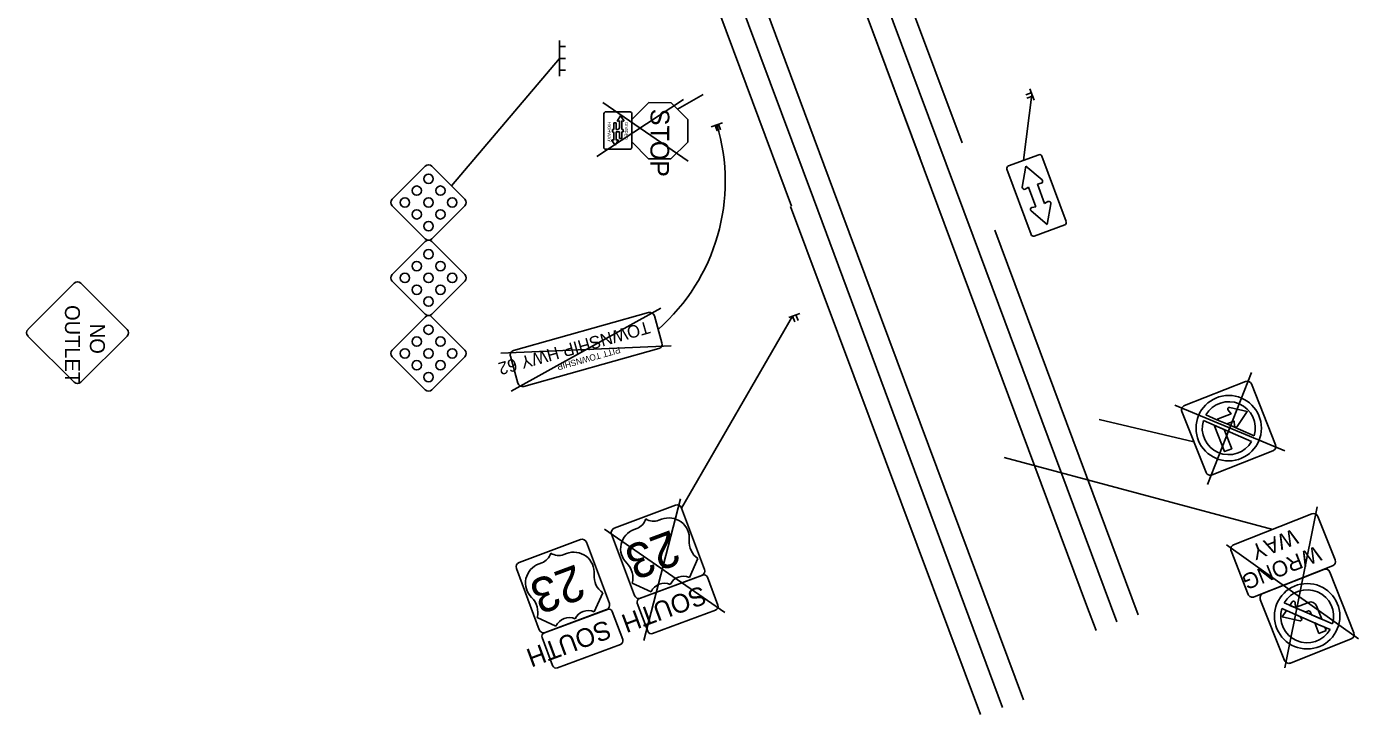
# Model space of a CAD drawing. Extents: x 179840 to 180553, y 300239 to 301090.
# Drawn here: x 179840 to 180553, y 300239 to 300607 of the extents above; entities that cross this region are included whole.
import ezdxf

# ---------------------------------------------------------------- set-up
doc = ezdxf.new("R2010")
doc.units = 0
for name, color, linetype in [('DR_P_Ditch', 7, 'Continuous'), ('MT_P_CL_40', 7, 'Continuous'), ('PM_P_Edge_Line', 7, 'Continuous'), ('PV_P_Saw_Cut_Line', 7, 'Continuous'), ('PV_X_Shoulder_Aggregate', 7, 'Continuous'), ('RW_P_Const_Limits', 7, 'Continuous')]:
    doc.layers.add(name, color=color, linetype=linetype)

msp = doc.modelspace()

# ---------------------------------------------------------------- linework, layer by layer
at = {"layer": 'DR_P_Ditch'}
for p, q in [((180407.15, 300297.25), (180248.33, 300723.77)), ((180271.8, 300519.09), (180373.45, 300246.68)), ((180248.77, 300510.52), (180350.47, 300238.9)), ((180358.06, 300497.86), (180434.85, 300292.18)), ((180407.15, 300297.25), (180412.37, 300283.81))]:
    msp.add_line(p, q, dxfattribs=at)
at = {"layer": 'MT_P_CL_40'}
for p, q in [((180346.46, 300494.63), (180276.74, 300681.88)), ((180261.02, 300514.81), (180362.15, 300242.51)), ((180346.46, 300494.63), (180423.45, 300288.43))]:
    msp.add_line(p, q, dxfattribs=at)
at = {"layer": 'PM_P_Edge_Line'}
for p, q in [((180200.42, 300919.36), (180340.54, 300544.7)), ((180178.69, 300911.24), (180318.13, 300536.33)), ((180132.45, 300894.04), (180271.8, 300519.09)), ((180179.58, 300698.16), (180249.31, 300510.72))]:
    msp.add_line(p, q, dxfattribs=at)
at = {"layer": 'PV_P_Saw_Cut_Line'}
for p, q in [((180125.19, 300592.98), (180125.19, 300599.38)), ((180125.19, 300596.18), (180128.39, 300596.18)), ((180125.19, 300589.84), (180067.4, 300521.71)), ((180125.19, 300586.64), (180125.19, 300593.04)), ((180125.19, 300589.84), (180128.39, 300589.84)), ((180125.19, 300580.24), (180125.19, 300586.64)), ((180125.19, 300583.44), (180128.39, 300583.44)), ((180191.46, 300567.82), (180145.18, 300537.41)), ((180148.39, 300566.3), (180193.95, 300534.81)), ((180099.3, 300411.83), (180179.42, 300456.17)), ((180247.8, 300451.13), (180253.79, 300453.38)), ((180251.69, 300452.59), (180252.82, 300449.6)), ((180249.9, 300451.92), (180251.02, 300448.92)), ((180250.79, 300452.26), (180250.79, 300452.26)), ((180093.74, 300432.15), (180184.99, 300435.97)), ((180471.9, 300361.92), (180495.43, 300421.74)), ((180513.18, 300379.96), (180454.45, 300404.23)), ((180170.37, 300278.42), (180189.97, 300354.16)), ((180513.27, 300263.75), (180530.54, 300349.87)), ((180149.35, 300337.93), (180213.65, 300293.36)), ((180128.9, 300324.92), (180127.43, 300324.38)), ((180552.59, 300279.24), (180482.09, 300329.59)), ((180115.72, 300320.02), (180114.25, 300319.47)), ((180143.81, 300293.79), (180148.41, 300303.84)), ((180113.26, 300290.76), (180123.31, 300286.16)), ((180117.13, 300282.53), (180150.87, 300295.08)), ((180153.44, 300293.91), (180159.02, 300278.91)), ((180121.53, 300264.96), (180115.95, 300279.96)), ((180157.84, 300276.34), (180124.1, 300263.79))]:
    msp.add_line(p, q, dxfattribs=at)
for points in [[(180053.4, 300532.17), (180035.72, 300514.49)], [(180074.61, 300514.49), (180056.93, 300532.17)], [(180035.72, 300510.96), (180053.4, 300493.28)], [(180056.93, 300493.28), (180074.61, 300510.96)], [(180053.4, 300491.82), (180035.72, 300474.14)], [(180074.61, 300474.14), (180056.93, 300491.82)], [(179840.84, 300444.84), (179865.59, 300469.59)], [(179869.13, 300469.59), (179893.88, 300444.84)], [(180035.72, 300470.6), (180053.4, 300452.92)], [(180056.93, 300452.92), (180074.61, 300470.6)], [(180053.4, 300451.46), (180035.72, 300433.78)], [(180074.61, 300433.78), (180056.93, 300451.46)], [(179865.59, 300416.56), (179840.84, 300441.3)], [(179893.88, 300441.3), (179869.13, 300416.56)], [(180035.72, 300430.25), (180053.4, 300412.57)], [(180056.93, 300412.57), (180074.61, 300430.25)], [(180136.45, 300332.4), (180103.65, 300320.2)], [(180151.87, 300298.12), (180139.67, 300330.93)], [(180102.18, 300316.98), (180114.38, 300284.18)], [(180117.59, 300282.71), (180150.4, 300294.91)]]:
    msp.add_lwpolyline(points, dxfattribs=at)
for centre in [(180055.16, 300525.39), (180048.83, 300519.06), (180061.5, 300519.06), (180042.5, 300512.73), (180055.16, 300512.73), (180067.83, 300512.73), (180048.83, 300506.39), (180055.16, 300500.06), (180061.5, 300506.39), (180048.83, 300478.7), (180055.16, 300485.04), (180061.5, 300478.7), (180042.5, 300472.37), (180055.16, 300472.37), (180067.83, 300472.37), (180048.83, 300466.04), (180061.5, 300466.04), (180055.16, 300459.7), (180055.16, 300444.68), (180048.83, 300438.35), (180061.5, 300438.35), (180042.5, 300432.01), (180055.16, 300432.01), (180067.83, 300432.01), (180048.83, 300425.68), (180061.5, 300425.68), (180055.16, 300419.35)]:
    msp.add_circle(centre, 2.5, dxfattribs=at)
for centre, radius, start, end in [((180055.16, 300530.4), 2.5, 45, 135), ((180037.49, 300512.73), 2.5, 135, 225), ((180072.84, 300512.73), 2.5, 315, 45), ((180055.16, 300495.05), 2.5, 225, 315), ((180055.16, 300490.05), 2.5, 45, 135), ((180037.49, 300472.37), 2.5, 135, 225), ((180072.84, 300472.37), 2.5, 315, 45), ((179867.36, 300467.82), 2.5, 45, 135), ((180055.16, 300454.69), 2.5, 225, 315), ((180055.16, 300449.69), 2.5, 45, 135), ((179842.61, 300443.07), 2.5, 135, 225), ((179892.11, 300443.07), 2.5, 315, 45), ((180037.49, 300432.01), 2.5, 135, 225), ((180072.84, 300432.01), 2.5, 315, 45), ((179867.36, 300418.32), 2.5, 225, 315), ((180055.16, 300414.34), 2.5, 225, 315), ((180137.32, 300330.06), 2.5, 20.40473, 110.40473), ((180112.99, 300327.34), 7.81, 290.40473, 343.53483), ((180124.71, 300331.7), 7.81, 237.27462, 290.40473), ((180132.82, 300314.71), 10.94, 355.23665, 111.04299), ((180104.52, 300317.85), 2.5, 110.40473, 200.40473), ((180117.95, 300309.18), 10.94, 109.76646, 225.57281), ((180154.62, 300312.84), 10.94, 174.95185, 235.40566), ((180102.68, 300293.52), 10.94, 345.4038, 45.8576), ((180149.53, 300297.25), 2.5, 290.40473, 20.40473), ((180130.38, 300282.84), 7.81, 65.97772, 154.83173), ((180140.63, 300286.66), 7.81, 65.97772, 154.83173), ((180151.56, 300293.21), 2, 20.40473, 110.40473), ((180116.72, 300285.05), 2.5, 200.40473, 290.40473), ((180117.82, 300280.66), 2, 110.40473, 200.40473), ((180157.14, 300278.21), 2, 290.40473, 20.40473), ((180123.4, 300265.66), 2, 200.40473, 290.40473)]:
    msp.add_arc(centre, radius, start, end, dxfattribs=at)
at = {"layer": 'PV_X_Shoulder_Aggregate'}
msp.add_line((180191.6, 300700.84), (180261.02, 300514.81), dxfattribs=at)
at = {"layer": 'RW_P_Const_Limits'}
for p, q in [((180376.82, 300573.5), (180379.06, 300567.5)), ((180188.4, 300562.62), (180202.01, 300570.48)), ((180373.49, 300535.3), (180377.94, 300570.5)), ((180377.61, 300571.4), (180374.61, 300570.28)), ((180378.28, 300569.6), (180375.28, 300568.48)), ((180377.94, 300570.5), (180377.94, 300570.5)), ((180148.86, 300542.25), (180148.94, 300560.25)), ((180149.95, 300561.24), (180162.95, 300561.18)), ((180163.94, 300560.18), (180163.86, 300542.18)), ((180172.97, 300566.14), (180163.93, 300557.18)), ((180184.97, 300566.08), (180172.97, 300566.14)), ((180193.93, 300557.04), (180184.97, 300566.08)), ((180154.34, 300555.39), (180154.32, 300551.85)), ((180155.59, 300555.38), (180154.34, 300555.39)), ((180155.57, 300551.84), (180155.59, 300555.38)), ((180157.9, 300559.12), (180156.24, 300556.61)), ((180156.57, 300556.16), (180157.26, 300556.35)), ((180157.26, 300556.35), (180157.25, 300552.67)), ((180159.54, 300556.6), (180157.9, 300559.12)), ((180158.49, 300551.83), (180158.51, 300556.34)), ((180158.51, 300556.34), (180159.19, 300556.15)), ((180159.53, 300556.6), (180159.54, 300556.6)), ((180163.93, 300557.18), (180163.87, 300545.18)), ((180193.87, 300545.04), (180193.93, 300557.04)), ((180206.41, 300553.23), (180212.42, 300555.42)), ((180208.52, 300554), (180209.61, 300550.99)), ((180209.42, 300554.33), (180209.42, 300554.33)), ((180210.32, 300554.66), (180211.41, 300551.65)), ((180153.27, 300545.83), (180154.91, 300543.31)), ((180153.49, 300551.85), (180153.48, 300550.6)), ((180153.48, 300550.6), (180153.49, 300550.6)), ((180154.32, 300551.85), (180153.49, 300551.85)), ((180154.3, 300546.1), (180153.61, 300546.3)), ((180154.31, 300549.77), (180154.3, 300546.1)), ((180154.91, 300543.31), (180156.57, 300545.81)), ((180155.55, 300546.09), (180155.57, 300550.59)), ((180156.24, 300546.28), (180155.55, 300546.09)), ((180156.41, 300551.84), (180155.57, 300551.84)), ((180155.57, 300550.59), (180157.24, 300550.59)), ((180157.24, 300550.59), (180157.22, 300547.05)), ((180157.22, 300547.05), (180158.47, 300547.04)), ((180158.47, 300547.04), (180158.49, 300550.58)), ((180159.32, 300551.83), (180158.49, 300551.83)), ((180158.49, 300550.58), (180159.32, 300550.58)), ((180159.32, 300550.58), (180159.32, 300551.83)), ((180163.87, 300545.18), (180172.83, 300536.14)), ((180184.83, 300536.08), (180193.87, 300545.04)), ((180162.85, 300541.18), (180149.85, 300541.24)), ((180184.83, 300536.08), (180172.83, 300536.14)), ((180172.83, 300536.14), (180184.83, 300536.08)), ((180172.83, 300536.14), (180184.83, 300536.08)), ((180374.64, 300532.17), (180372.77, 300520.97)), ((180383.34, 300524.86), (180374.64, 300532.17)), ((180374.27, 300519.87), (180376.15, 300520.85)), ((180376.15, 300520.85), (180379.97, 300510.49)), ((180384.66, 300512.22), (180380.84, 300522.58)), ((180380.85, 300522.58), (180382.91, 300523.06)), ((180379.97, 300510.49), (180377.91, 300510)), ((180386.54, 300513.19), (180384.66, 300512.22)), ((180384.66, 300512.22), (180384.66, 300512.22)), ((180386.17, 300500.89), (180388.05, 300512.09)), ((180377.48, 300508.19), (180386.17, 300500.89)), ((180249.9, 300451.92), (180190.55, 300349.29)), ((180483.74, 300403.02), (180493.16, 300400.86)), ((180464.63, 300384.63), (180413.84, 300396.7)), ((180469.65, 300396.05), (180495.48, 300384.88)), ((180477.67, 300396.97), (180484.52, 300399.68)), ((180482.17, 300394.27), (180486.06, 300395.81)), ((180482.9, 300401.69), (180484.52, 300399.68)), ((180486.25, 300393.24), (180486.06, 300395.81)), ((180487.77, 300392.84), (180493.16, 300400.86)), ((180475.8, 300392.64), (180481.02, 300379.47)), ((180480.85, 300391.21), (180484.89, 300381)), ((180506.77, 300337.88), (180363.01, 300376.32)), ((180481.02, 300379.47), (180484.89, 300381)), ((180166.6, 300338.38), (180165.14, 300337.83)), ((180179.78, 300343.28), (180178.32, 300342.74)), ((180194.7, 300312.15), (180199.29, 300322.2)), ((180168.01, 300300.89), (180201.75, 300313.44)), ((180204.32, 300312.27), (180209.9, 300297.27)), ((180164.15, 300309.13), (180174.19, 300304.53)), ((180172.41, 300283.33), (180166.83, 300298.32)), ((180512.93, 300298.51), (180538.76, 300287.34)), ((180517.26, 300299.08), (180515.99, 300297.18)), ((180517.26, 300299.08), (180515.99, 300297.18)), ((180515.99, 300297.18), (180524.13, 300293.66)), ((180518.78, 300298.67), (180518.98, 300296.1)), ((180518.98, 300296.1), (180518.78, 300298.67)), ((180525.83, 300298.82), (180518.98, 300296.1)), ((180525.83, 300298.82), (180518.98, 300296.1)), ((180530.15, 300296.95), (180532.97, 300289.84)), ((180532.97, 300289.84), (180530.15, 300296.95)), ((180208.72, 300294.7), (180174.98, 300282.15)), ((180514.1, 300294.37), (180511.87, 300291.05)), ((180514.1, 300294.37), (180511.87, 300291.05)), ((180521.3, 300288.89), (180511.87, 300291.05)), ((180511.87, 300291.05), (180521.3, 300288.89)), ((180521.33, 300291.24), (180514.1, 300294.37)), ((180522.13, 300290.23), (180521.32, 300291.23)), ((180522.13, 300290.23), (180521.32, 300291.23)), ((180525.47, 300294.19), (180524.13, 300293.66)), ((180524.13, 300293.66), (180525.47, 300294.19)), ((180527.03, 300293.52), (180527.56, 300292.18)), ((180527.03, 300293.52), (180527.56, 300292.18)), ((180527.56, 300292.18), (180532.82, 300289.9)), ((180532.82, 300289.9), (180532.97, 300289.84)), ((180529.3, 300287.8), (180531.5, 300282.24)), ((180531.5, 300286.84), (180529.3, 300287.8)), ((180529.3, 300287.8), (180531.5, 300282.24)), ((180534.7, 300285.46), (180531.5, 300286.84)), ((180535.37, 300283.77), (180531.5, 300282.24)), ((180531.5, 300282.24), (180535.37, 300283.77)), ((180534.7, 300285.46), (180535.37, 300283.77)), ((180535.37, 300283.77), (180534.7, 300285.46))]:
    msp.add_line(p, q, dxfattribs=at)
for points in [[(180365.36, 300532.3), (180381.62, 300538.29)], [(180383.33, 300537.5), (180396.25, 300502.48)], [(180377.48, 300495.56), (180364.57, 300530.59)], [(180395.46, 300500.76), (180379.2, 300494.77)], [(180172.87, 300453.83), (180100.67, 300433.56)], [(180180.01, 300437.65), (180175.96, 300452.09)], [(180106.07, 300414.3), (180178.28, 300434.57)], [(180098.93, 300430.47), (180102.99, 300416.03)], [(180492.13, 300417.04), (180459.59, 300404.15)], [(180508.27, 300383.09), (180495.38, 300415.63)], [(180487.77, 300392.84), (180493.16, 300400.86), (180483.74, 300403.02)], [(180458.19, 300400.9), (180471.08, 300368.36)], [(180476.91, 300396.54), (180470.98, 300399.11)], [(180496.8, 300387.94), (180482.17, 300394.27), (180476.91, 300396.54)], [(180476.91, 300396.54), (180482.17, 300394.27), (180486.06, 300395.81), (180486.25, 300393.24)], [(180482.9, 300401.69), (180484.52, 300399.68), (180477.67, 300396.97)], [(180480.85, 300391.21), (180475.59, 300393.49)], [(180475.8, 300392.64), (180481.02, 300379.47), (180484.89, 300381), (180480.85, 300391.21)], [(180474.32, 300366.96), (180506.86, 300379.85)], [(180187.34, 300350.76), (180154.53, 300338.56)], [(180202.75, 300316.48), (180190.55, 300349.29)], [(180527.69, 300346.16), (180485.85, 300329.59)], [(180540.14, 300321.52), (180530.93, 300344.76)], [(180153.06, 300335.34), (180165.26, 300302.54)], [(180484.45, 300326.35), (180493.65, 300303.1)], [(180496.9, 300301.7), (180538.74, 300318.27)], [(180168.48, 300301.07), (180201.28, 300313.27)], [(180501.55, 300303.54), (180534.09, 300316.43)], [(180537.33, 300315.03), (180550.22, 300282.49)], [(180513.03, 300267.76), (180500.14, 300300.3)], [(180511.61, 300295.45), (180526.24, 300289.12), (180531.5, 300286.84)], [(180521.32, 300291.23), (180521.33, 300291.24)], [(180531.5, 300286.84), (180537.43, 300284.28)], [(180548.82, 300279.24), (180516.28, 300266.35)]]:
    msp.add_lwpolyline(points, dxfattribs=at)
for centre in [(180483.23, 300392), (180525.18, 300291.39)]:
    msp.add_circle(centre, 17.5, dxfattribs=at)
for centre, radius, start, end in [((180149.94, 300560.24), 1, 89.73629, 179.73629), ((180162.94, 300560.18), 1, 359.73629, 89.73629), ((180156.49, 300556.45), 0.305, 146.49664, 285.36327), ((180156.41, 300552.67), 0.832, 269.73629, 359.73629), ((180159.27, 300556.44), 0.305, 254.10931, 32.97593), ((180108.69, 300524.01), 105.19, 311.20406, 16.74943), ((180153.53, 300546), 0.305, 74.10931, 212.97593), ((180153.48, 300549.77), 0.832, 359.73629, 89.73629), ((180156.32, 300545.98), 0.305, 326.49664, 105.36327), ((180149.86, 300542.24), 1, 179.73629, 269.73629), ((180162.86, 300542.18), 1, 269.73629, 359.73629), ((180382.08, 300537.04), 1.33, 20.2366, 110.2366), ((180365.82, 300531.05), 1.33, 110.2366, 200.2366), ((180382.67, 300524.07), 1.04, 283.11158, 49.98148), ((180373.8, 300520.8), 1.04, 170.49172, 297.36161), ((180378.15, 300508.99), 1.04, 103.11158, 229.98148), ((180387.02, 300512.26), 1.04, 350.49172, 117.36161), ((180395, 300502.01), 1.33, 290.2366, 20.2366), ((180378.73, 300496.02), 1.33, 200.2366, 290.2366), ((180173.55, 300451.42), 2.5, 15.67937, 105.67937), ((180101.34, 300431.15), 2.5, 105.67937, 195.67937), ((180177.6, 300436.98), 2.5, 285.67937, 15.67937), ((180493.05, 300414.71), 2.5, 21.60959, 111.60959), ((180105.39, 300416.71), 2.5, 195.67937, 285.67937), ((180460.51, 300401.82), 2.5, 111.60959, 201.60959), ((180483.23, 300392), 14.17, 343.36591, 149.85326), ((180483.23, 300392), 14.17, 343.36591, 149.85326), ((180483.55, 300402.21), 0.833, 77.09331, 218.97142), ((180483.55, 300402.21), 0.833, 77.09331, 218.97142), ((180483.23, 300392), 14.17, 163.36591, 329.85326), ((180478.9, 300393.87), 3.33, 111.60959, 126.60959), ((180478.9, 300393.87), 3.33, 111.60959, 126.60959), ((180478.9, 300393.87), 3.33, 186.60959, 201.60959), ((180478.9, 300393.87), 3.33, 186.60959, 201.60959), ((180487.08, 300393.3), 0.833, 184.24775, 326.12586), ((180487.08, 300393.3), 0.833, 184.24775, 326.12586), ((180505.94, 300382.17), 2.5, 291.60959, 21.60959), ((180473.4, 300369.28), 2.5, 201.60959, 291.60959), ((180188.21, 300348.42), 2.5, 20.40473, 110.40473), ((180528.61, 300343.84), 2.5, 21.60959, 111.60959), ((180155.4, 300336.21), 2.5, 110.40473, 200.40473), ((180163.88, 300345.7), 7.81, 290.40473, 343.53483), ((180175.59, 300350.06), 7.81, 237.27462, 290.40473), ((180183.71, 300333.07), 10.94, 355.23665, 111.04299), ((180168.84, 300327.54), 10.94, 109.76646, 225.57281), ((180205.5, 300331.2), 10.94, 174.95185, 235.40566), ((180486.77, 300327.27), 2.5, 111.60959, 201.60959), ((180153.56, 300311.88), 10.94, 345.4038, 45.8576), ((180537.81, 300320.6), 2.5, 291.60959, 21.60959), ((180191.52, 300305.02), 7.81, 65.97772, 154.83173), ((180200.41, 300315.61), 2.5, 290.40473, 20.40473), ((180202.45, 300311.57), 2, 20.40473, 110.40473), ((180535.01, 300314.11), 2.5, 21.60959, 111.60959), ((180181.26, 300301.2), 7.81, 65.97772, 154.83173), ((180495.98, 300304.02), 2.5, 201.60959, 291.60959), ((180502.47, 300301.22), 2.5, 111.60959, 201.60959), ((180525.18, 300291.39), 14.17, 343.36591, 149.85326), ((180167.61, 300303.41), 2.5, 200.40473, 290.40473), ((180168.71, 300299.02), 2, 110.40473, 200.40473), ((180208.03, 300296.58), 2, 290.40473, 20.40473), ((180517.95, 300298.61), 0.833, 4.24775, 146.12586), ((180517.95, 300298.61), 0.833, 4.24775, 146.12586), ((180527.05, 300295.72), 3.33, 21.60959, 111.60959), ((180527.05, 300295.72), 3.33, 21.60959, 111.60959), ((180525.18, 300291.39), 14.17, 163.36591, 329.85326), ((180525.18, 300291.39), 14.17, 163.36591, 329.85326), ((180521.48, 300289.7), 0.833, 257.09331, 38.97142), ((180521.48, 300289.7), 0.833, 257.09331, 38.97142), ((180525.91, 300293.08), 1.2, 21.60959, 111.60959), ((180525.91, 300293.08), 1.2, 21.60959, 111.60959), ((180174.29, 300284.02), 2, 200.40473, 290.40473), ((180547.9, 300281.57), 2.5, 291.60959, 21.60959), ((180515.36, 300268.68), 2.5, 201.60959, 291.60959)]:
    msp.add_arc(centre, radius, start, end, dxfattribs=at)

# ---------------------------------------------------------------- texts
at = {"layer": 'PV_P_Saw_Cut_Line'}
for s, height, rotation, p in [('OUTLET', 8, 270, (179860.62, 300457.84)), ('NO', 8, 270, (179873.96, 300447.81)), ('23', 18.75, 200.40473, (180134.16, 300319.38)), ('SOUTH', 10, 200.40473, (180150.46, 300289.6))]:
    msp.add_text(s, height=height, rotation=rotation, dxfattribs=at).set_placement(p)
at = {"layer": 'RW_P_Const_Limits'}
for s, height, rotation, p in [('STOP', 10, 269.73629, (180173.95, 300562.88)), ('HIGHWAY', 1.667, 269.73629, (180151.01, 300556.03)), ('DIVIDED', 1.667, 269.73629, (180160.17, 300555.67)), ('TOWNSHIP HWY 62', 6.6667, 195.67937, (180172.47, 300449.38)), ('PITT TOWNSHIP', 3.3333, 195.67937, (180157.22, 300435.58)), ('23', 18.75, 200.40473, (180185.04, 300337.74)), ('WAY', 8.375, 201.60959, (180518.07, 300338.34)), ('WRONG', 8.375, 201.60959, (180530.53, 300329.29)), ('SOUTH', 10, 200.40473, (180201.34, 300307.96))]:
    msp.add_text(s, height=height, rotation=rotation, dxfattribs=at).set_placement(p)

doc.saveas('drawing.dxf')
